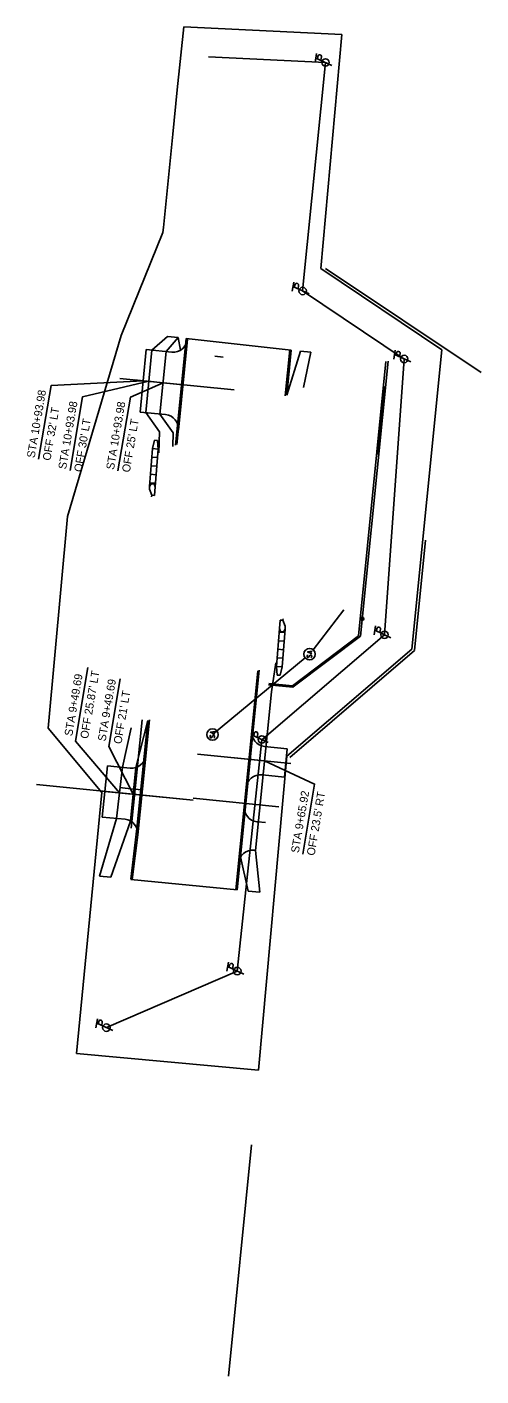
# Model space of a CAD drawing. Extents: x 1620309 to 1621039, y 607069 to 607940.
# Drawn here: x 1620880.5 to 1621039.3, y 607069.1 to 607541 of the extents above; entities that cross this region are included whole.
import ezdxf

# ---------------------------------------------------------------- set-up
doc = ezdxf.new("R2010")
doc.units = 0
for name, color, linetype in [('BR_P_Rail_Object', 7, 'Continuous'), ('Default', 7, 'Continuous'), ('GE_P_Driveway_CL', 7, 'Continuous'), ('PV_P_Curb', 7, 'Continuous'), ('PV_P_Drive', 7, 'Continuous'), ('PV_P_EOP', 7, 'Continuous'), ('PV_P_Joint', 7, 'Continuous'), ('PV_P_Walk', 7, 'Continuous'), ('RW_P_Const_Limits', 7, 'Continuous'), ('RW_P_Esmt_TMP', 7, 'Continuous'), ('SC_Scratch1', 7, 'Continuous'), ('SC_Scratch13', 7, 'Continuous'), ('UT_P_Electric', 7, 'Continuous'), ('UT_P_Gas', 7, 'Continuous'), ('UT_P_Gas_Cells', 7, 'Continuous'), ('UT_P_Misc_Cells', 7, 'Continuous'), ('UT_P_Sanitary', 7, 'Continuous'), ('UT_P_Sanitary_Cells', 7, 'Continuous'), ('UT_X_Gas', 7, 'Continuous')]:
    doc.layers.add(name, color=color, linetype=linetype)

msp = doc.modelspace()

# ---------------------------------------------------------------- linework, layer by layer
at = {"layer": 'BR_P_Rail_Object'}
for p, q in [((1620925.16, 607396.44), (1620924.43, 607393.49)), ((1620925.16, 607396.44), (1620926.15, 607396.37)), ((1620926.15, 607396.37), (1620926.42, 607393.34)), ((1620923.42, 607380.28), (1620924.43, 607393.49)), ((1620924.2, 607390.5), (1620926.2, 607390.35)), ((1620924.43, 607393.49), (1620926.42, 607393.34)), ((1620925.41, 607380.13), (1620926.42, 607393.34)), ((1620923.74, 607384.52), (1620925.74, 607384.36)), ((1620923.97, 607387.51), (1620925.97, 607387.36)), ((1620923.42, 607380.28), (1620923.34, 607379.28)), ((1620923.99, 607381.24), (1620923.42, 607380.28)), ((1620923.52, 607381.53), (1620925.51, 607381.37)), ((1620924.99, 607381.16), (1620923.99, 607381.24)), ((1620925.41, 607380.13), (1620924.99, 607381.16)), ((1620925.19, 607377.14), (1620925.41, 607380.13)), ((1620923.34, 607379.28), (1620924.19, 607377.21)), ((1620924.19, 607377.21), (1620924.13, 607376.66)), ((1620924.19, 607377.21), (1620925.19, 607377.14)), ((1620969.05, 607333.52), (1620968.82, 607330.53)), ((1620970.05, 607333.45), (1620969.05, 607333.52)), ((1620970.05, 607333.45), (1620970.11, 607334)), ((1620970.89, 607331.38), (1620970.05, 607333.45)), ((1620968.82, 607330.53), (1620967.81, 607317.32)), ((1620970.72, 607329.13), (1620968.73, 607329.28)), ((1620968.82, 607330.53), (1620969.25, 607329.5)), ((1620969.25, 607329.5), (1620970.24, 607329.42)), ((1620970.82, 607330.38), (1620969.81, 607317.17)), ((1620970.24, 607329.42), (1620970.82, 607330.38)), ((1620970.82, 607330.38), (1620970.89, 607331.38)), ((1620970.27, 607323.15), (1620968.27, 607323.3)), ((1620970.49, 607326.14), (1620968.5, 607326.29)), ((1620970.04, 607320.16), (1620968.04, 607320.31)), ((1620968.08, 607314.29), (1620967.81, 607317.32)), ((1620969.81, 607317.17), (1620967.81, 607317.32)), ((1620969.08, 607314.21), (1620968.08, 607314.29)), ((1620969.08, 607314.21), (1620969.81, 607317.17))]:
    msp.add_line(p, q, dxfattribs=at)
at = {"layer": 'Default'}
for p, q in [((1620923, 607417.07), (1620929.04, 607416.46)), ((1620958.66, 607284.79), (1620959.12, 607284.74))]:
    msp.add_line(p, q, dxfattribs=at)
at = {"layer": 'GE_P_Driveway_CL'}
for p, q in [((1620953.01, 607414.06), (1620913.02, 607418.07)), ((1620963.61, 607284.29), (1620940.23, 607286.63)), ((1620940.23, 607286.63), (1620972.83, 607283.37)), ((1620938.61, 607270.49), (1620883.89, 607275.97))]:
    msp.add_line(p, q, dxfattribs=at)
at = {"layer": 'PV_P_Curb'}
for p, q in [((1620932.47, 607394.67), (1620936.22, 607432.03)), ((1620971.42, 607412.24), (1620972.99, 607427.96)), ((1620954.06, 607239.1), (1620961.8, 607316)), ((1620917.03, 607260.77), (1620920.83, 607298.62)), ((1620919.02, 607260.57), (1620922.82, 607298.42)), ((1620916.88, 607242.84), (1620919.02, 607260.57))]:
    msp.add_line(p, q, dxfattribs=at)
at = {"layer": 'PV_P_Drive'}
for p, q in [((1620922.27, 607428.2), (1620920.07, 607406.31)), ((1620922.27, 607428.2), (1620931.22, 607427.3)), ((1620935.09, 607415.86), (1620917.99, 607417.58)), ((1620920.07, 607406.31), (1620929.03, 607405.41)), ((1620957.14, 607274.89), (1620959.14, 607294.79)), ((1620971.57, 607288.51), (1620963.62, 607289.32)), ((1620970.58, 607278.57), (1620971.57, 607288.51)), ((1620906.87, 607264.62), (1620908.66, 607282.53)), ((1620908.66, 607282.53), (1620916.62, 607281.74)), ((1620962.95, 607279.33), (1620962.62, 607279.37)), ((1620962.95, 607279.33), (1620970.58, 607278.57)), ((1620906.87, 607264.62), (1620914.83, 607263.83)), ((1620961.3, 607262.93), (1620960.98, 607262.96)), ((1620961.3, 607262.93), (1620964, 607262.66)), ((1620960.48, 607252.96), (1620959.98, 607253.01))]:
    msp.add_line(p, q, dxfattribs=at)
for points in [[(1620921.17, 607417.25), (1620888.97, 607415.58), (1620884.6, 607389.87)], [(1620923.16, 607417.05), (1620899.96, 607411.6), (1620895.59, 607385.89)], [(1620928.13, 607416.55), (1620916.71, 607411.46), (1620912.34, 607385.75)], [(1620912.87, 607273.07), (1620897.51, 607291.18), (1620901.88, 607316.94)], [(1620917.72, 607272.58), (1620909.18, 607289.35), (1620913.18, 607312.92)], [(1620963.61, 607284.29), (1620981.12, 607276.15), (1620976.96, 607251.67)]]:
    msp.add_lwpolyline(points, dxfattribs=at)
for centre, start, end in [((1620931.72, 607432.27), 264.274, 354.274), ((1620928.53, 607400.43), 354.274, 84.274), ((1620964.11, 607294.29), 174.274, 264.274), ((1620917.12, 607286.71), 264.274, 354.274), ((1620962.12, 607274.39), 84.274, 174.274), ((1620961.48, 607267.93), 174.274, 264.274), ((1620914.33, 607258.85), 354.274, 84.274), ((1620959.48, 607248.03), 84.274, 174.274)]:
    msp.add_arc(centre, 5, start, end, dxfattribs=at)
at = {"layer": 'PV_P_EOP'}
for p, q in [((1620933, 607394.91), (1620936.71, 607431.98)), ((1620936.22, 607432.03), (1620972.99, 607427.96)), ((1620970.89, 607412), (1620972.5, 607428.02)), ((1620949.15, 607425.5), (1620946.22, 607425.8)), ((1620958.09, 607284.31), (1620961.24, 607315.75)), ((1620919.3, 607258.35), (1620923.35, 607298.66)), ((1620953.56, 607239.15), (1620958.09, 607284.32)), ((1620917.37, 607242.78), (1620919.3, 607258.35)), ((1620917.97, 607249.13), (1620917.53, 607249.17)), ((1620954.06, 607239.1), (1620916.9, 607242.82))]:
    msp.add_line(p, q, dxfattribs=at)
at = {"layer": 'PV_P_Joint'}
msp.add_line((1620933.5, 607399.94), (1620936.69, 607431.78), dxfattribs=at)
at = {"layer": 'PV_P_Walk'}
for p, q in [((1620933.39, 607432.35), (1620929.73, 607432.75)), ((1620934.28, 607427.98), (1620933.39, 607432.35)), ((1620971.42, 607412.24), (1620976.16, 607427.61)), ((1620976.16, 607427.61), (1620979.79, 607427.21)), ((1620977.21, 607414.85), (1620979.79, 607427.21)), ((1620905.87, 607243.93), (1620911.84, 607264.13)), ((1620909.86, 607243.53), (1620916.78, 607263.21)), ((1620960.47, 607252.95), (1620961.94, 607238.31)), ((1620955.21, 607250.64), (1620957.94, 607238.71)), ((1620905.87, 607243.93), (1620909.86, 607243.53)), ((1620961.94, 607238.31), (1620957.94, 607238.71))]:
    msp.add_line(p, q, dxfattribs=at)
for points in [[(1620926.68, 607392.06), (1620926.86, 607399.41), (1620922.06, 607406.11), (1620924.26, 607428), (1620929.73, 607432.75)], [(1620933.39, 607432.35), (1620929.23, 607427.5), (1620927.04, 607405.61), (1620931.71, 607399.08), (1620931.59, 607394.28)], [(1620960.47, 607252.96), (1620966.03, 607308.41), (1620967.56, 607318.6)], [(1620911.84, 607264.13), (1620913.9, 607282.01), (1620917.03, 607295.81)], [(1620916.78, 607263.21), (1620918.66, 607281.95), (1620922.82, 607298.42)]]:
    msp.add_lwpolyline(points, dxfattribs=at)
at = {"layer": 'RW_P_Const_Limits'}
for p, q in [((1620935.34, 607541.01), (1620990.7, 607538.34)), ((1620983.27, 607456.47), (1620990.7, 607538.34)), ((1620913.48, 607433.13), (1620928.09, 607469.06)), ((1621025.61, 607428.08), (1620983.27, 607456.47)), ((1620894.71, 607369.71), (1620913.48, 607433.13)), ((1621015.12, 607323.4), (1621025.61, 607428.08)), ((1620887.99, 607295.69), (1620894.71, 607369.71)), ((1620971.45, 607285.93), (1621015.12, 607323.4)), ((1620906.73, 607273.2), (1620887.99, 607295.69)), ((1620961.48, 607176.07), (1620971.45, 607285.93)), ((1620897.91, 607181.84), (1620906.73, 607273.2)), ((1620897.91, 607181.84), (1620961.48, 607176.07)), ((1620959.11, 607149.92), (1620951, 607069.06))]:
    msp.add_line(p, q, dxfattribs=at)
msp.add_lwpolyline([(1620928.11, 607469.1), (1620928.28, 607470.9), (1620931.57, 607503.52), (1620933.1, 607518.99), (1620935.34, 607541.01)], dxfattribs=at)
at = {"layer": 'RW_P_Esmt_TMP'}
for p, q in [((1621039.32, 607420.1), (1620984.91, 607456.57)), ((1621016.07, 607322.91), (1621019.94, 607361.52)), ((1620972.41, 607285.43), (1621016.07, 607322.91))]:
    msp.add_line(p, q, dxfattribs=at)
at = {"layer": 'SC_Scratch1'}
msp.add_lwpolyline([(1620920.89, 607274.11), (1620917.9, 607274.41), (1620912.92, 607274.91)], dxfattribs=at)
at = {"layer": 'SC_Scratch13'}
for p, q in [((1620913.02, 607418.07), (1620953.01, 607414.06)), ((1620906.63, 607273.69), (1620938.61, 607270.49)), ((1620968.58, 607268.19), (1620938.68, 607271.19))]:
    msp.add_line(p, q, dxfattribs=at)
at = {"layer": 'UT_P_Electric'}
msp.add_lwpolyline([(1620943.98, 607530.58), (1620984.94, 607528.6), (1620976.95, 607448.66), (1621012.47, 607424.85), (1621005.57, 607328.38), (1620962.7, 607291.59), (1620954.09, 607210.73), (1620908.31, 607190.94)], dxfattribs=at)
at = {"layer": 'UT_P_Gas'}
for p, q in [((1621006.08, 607424.02), (1620996.45, 607328)), ((1621006.8, 607424.1), (1620997.16, 607327.93))]:
    msp.add_line(p, q, dxfattribs=at)
for points in [[(1620997.16, 607327.93), (1620974.07, 607310.5), (1620973.49, 607310.09), (1620965.06, 607310.92)], [(1620996.45, 607328), (1620973.37, 607310.57), (1620973.37, 607310.57), (1620965.11, 607311.39)]]:
    msp.add_lwpolyline(points, dxfattribs=at)
at = {"layer": 'UT_P_Gas_Cells'}
msp.add_circle((1620997.76, 607333.99), 0.581, dxfattribs=at)
at = {"layer": 'UT_P_Misc_Cells'}
for p, q in [((1620981.82, 607531.73), (1620981.28, 607528.58)), ((1620982.11, 607529.9), (1620982.26, 607530.74)), ((1620983.31, 607529.35), (1620983.51, 607530.52)), ((1620981.55, 607530.16), (1620987.2, 607527.57)), ((1620973.83, 607451.79), (1620973.3, 607448.64)), ((1620974.13, 607449.96), (1620974.27, 607450.8)), ((1620975.33, 607449.41), (1620975.53, 607450.58)), ((1620973.56, 607450.22), (1620979.21, 607447.63)), ((1621009.35, 607427.98), (1621008.81, 607424.83)), ((1621009.65, 607426.15), (1621009.79, 607426.99)), ((1621010.84, 607425.6), (1621011.04, 607426.77)), ((1621009.08, 607426.41), (1621014.73, 607423.82)), ((1621002.45, 607331.51), (1621001.91, 607328.36)), ((1621002.18, 607329.94), (1621007.82, 607327.35)), ((1621002.74, 607329.68), (1621002.88, 607330.52)), ((1621003.94, 607329.13), (1621004.14, 607330.3)), ((1620959.54, 607294.88), (1620959.01, 607291.72)), ((1620959.28, 607293.3), (1620964.92, 607290.71)), ((1620959.84, 607293.04), (1620959.98, 607293.88)), ((1620961.04, 607292.49), (1620961.24, 607293.67)), ((1620950.97, 607213.86), (1620950.44, 607210.71)), ((1620950.7, 607212.29), (1620956.35, 607209.7)), ((1620951.27, 607212.03), (1620951.41, 607212.86)), ((1620952.47, 607211.48), (1620952.67, 607212.65)), ((1620905.19, 607194.07), (1620904.65, 607190.92)), ((1620904.92, 607192.49), (1620910.56, 607189.9)), ((1620905.48, 607192.23), (1620905.62, 607193.07)), ((1620906.68, 607191.68), (1620906.88, 607192.86))]:
    msp.add_line(p, q, dxfattribs=at)
for centre in [(1620984.94, 607528.6), (1620976.95, 607448.66), (1621012.47, 607424.85), (1621005.57, 607328.38), (1620962.66, 607291.75), (1620954.09, 607210.73), (1620908.31, 607190.94)]:
    msp.add_circle(centre, 1.3, dxfattribs=at)
for centre in [(1620982.89, 607530.64), (1620974.9, 607450.7), (1621010.42, 607426.89), (1621003.52, 607330.42), (1620960.61, 607293.79), (1620952.04, 607212.77), (1620906.25, 607192.98)]:
    msp.add_arc(centre, 0.638, 349.2353, 171.4819, dxfattribs=at)
at = {"layer": 'UT_P_Sanitary'}
for p, q in [((1620991.39, 607337.13), (1620980.6, 607323.16)), ((1620977.84, 607320.31), (1620945.42, 607293.46))]:
    msp.add_line(p, q, dxfattribs=at)
at = {"layer": 'UT_P_Sanitary_Cells'}
for points in [[(1620978.66, 607321.32), (1620978.63, 607321.3), (1620978.6, 607321.26), (1620978.55, 607321.15), (1620978.52, 607321.02), (1620978.51, 607320.92), (1620978.5, 607320.88), (1620978.52, 607320.71), (1620978.58, 607320.57), (1620978.68, 607320.47), (1620978.77, 607320.43), (1620978.85, 607320.43), (1620978.95, 607320.44), (1620979.05, 607320.53), (1620979.49, 607321.18), (1620979.55, 607321.24), (1620979.6, 607321.26), (1620979.68, 607321.28), (1620979.76, 607321.27), (1620979.83, 607321.25), (1620979.88, 607321.23), (1620979.94, 607321.2), (1620979.99, 607321.17), (1620980.02, 607321.14), (1620980.06, 607321.1), (1620980.08, 607321.06), (1620980.1, 607321.01), (1620980.11, 607320.97), (1620980.11, 607320.86), (1620980.09, 607320.68), (1620980.05, 607320.57), (1620979.95, 607320.42), (1620979.86, 607320.32)], [(1620980.19, 607321.71), (1620978.65, 607322.37), (1620980.29, 607322.7)], [(1620979.9, 607322.61), (1620979.83, 607321.87)], [(1620946.24, 607293.59), (1620944.7, 607294.25), (1620946.34, 607294.58)], [(1620945.95, 607294.49), (1620945.87, 607293.75)], [(1620944.7, 607293.2), (1620944.68, 607293.18), (1620944.65, 607293.14), (1620944.6, 607293.03), (1620944.56, 607292.9), (1620944.55, 607292.8), (1620944.55, 607292.76), (1620944.57, 607292.59), (1620944.63, 607292.45), (1620944.72, 607292.35), (1620944.82, 607292.32), (1620944.89, 607292.31), (1620945, 607292.32), (1620945.09, 607292.42), (1620945.54, 607293.07), (1620945.6, 607293.12), (1620945.65, 607293.14), (1620945.73, 607293.16), (1620945.8, 607293.15), (1620945.87, 607293.13), (1620945.92, 607293.12), (1620945.98, 607293.09), (1620946.03, 607293.06), (1620946.07, 607293.03), (1620946.1, 607292.99), (1620946.12, 607292.95), (1620946.14, 607292.89), (1620946.15, 607292.85), (1620946.15, 607292.74), (1620946.13, 607292.56), (1620946.1, 607292.45), (1620945.99, 607292.3), (1620945.91, 607292.21)]]:
    msp.add_lwpolyline(points, dxfattribs=at)
for centre in [(1620979.38, 607321.58), (1620945.42, 607293.46)]:
    msp.add_circle(centre, 2, dxfattribs=at)
at = {"layer": 'UT_X_Gas'}
for p, q in [((1621002.85, 607391.36), (1621005.25, 607415.28)), ((1621003.41, 607391.52), (1621005.79, 607415.22))]:
    msp.add_line(p, q, dxfattribs=at)

# ---------------------------------------------------------------- texts
at = {"layer": 'PV_P_Drive'}
for s, p in [('STA 10+93.98', (1620883.22, 607390.1)), ("OFF 32' LT", (1620888.74, 607389.16)), ('STA 10+93.98', (1620894.21, 607386.13)), ('STA 10+93.98', (1620910.96, 607385.99)), ("OFF 30' LT", (1620899.73, 607385.19)), ("OFF 25' LT", (1620916.48, 607385.05)), ('STA 9+49.69', (1620896.36, 607292.79)), ("OFF 25.87' LT", (1620901.88, 607291.86)), ('STA 9+49.69', (1620908.03, 607290.97)), ("OFF 21' LT", (1620913.55, 607290.03)), ('STA 9+65.92', (1620975.58, 607251.9)), ("OFF 23.5' RT", (1620981.1, 607250.97))]:
    msp.add_text(s, height=2.8, rotation=80.3586, dxfattribs=at).set_placement(p)

doc.saveas('drawing.dxf')
